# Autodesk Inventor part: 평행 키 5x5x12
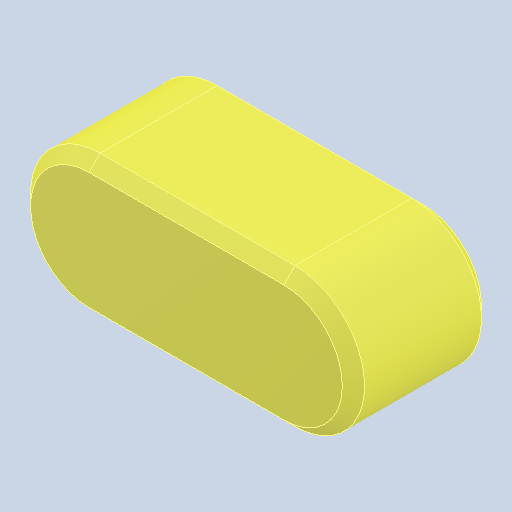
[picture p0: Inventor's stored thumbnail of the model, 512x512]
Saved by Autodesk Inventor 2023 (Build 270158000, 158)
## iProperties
Created: 2025-03
Part Number: 평행 키 5x5x12
Material: 강철, 연강
Description: 키 및 해당 키홈
Document SubType Name: Modeling
Designer: ADMIN_PC
Density: 7.85 g/cm^3
Appearance: 기본값
Author: jhkim
Sending System: Autodesk Inventor 2025
Preprocessor: ST-DEVELOPER v20
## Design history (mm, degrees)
feature "Solid1"
node "솔리드1"
